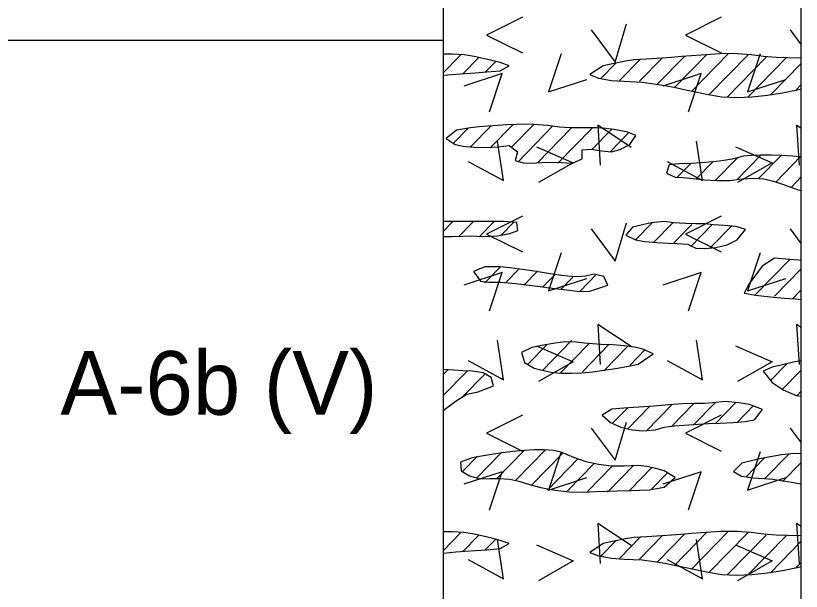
# Model space of a CAD drawing. Extents: x -0.01 to 0.83, y -0.63 to 1.27.
# Drawn here: x 0.7511 to 0.8333, y 0.6598 to 0.7201 of the extents above; entities that cross this region are included whole.
import ezdxf

# ---------------------------------------------------------------- set-up
doc = ezdxf.new("R2010")
doc.units = 0

msp = doc.modelspace()

# ---------------------------------------------------------------- linework, layer by layer
for points in [[(0, 0), (0.833332, 0), (0.833332, 1.274997), (0, 1.274997)], [(0, 0), (0.833332, 0), (0.833332, 1.274997), (0, 1.274997)], [(0, 0), (0.833332, 0), (0.833332, 1.274997), (0, 1.274997)], [(0, 0), (0.833332, 0), (0.833332, 1.274997), (0, 1.274997)], [(0, 0), (0.833332, 0), (0.833332, 1.274997), (0, 1.274997)], [(0.795832, 0.713822), (0.797147, 0.713933), (0.798141, 0.714006), (0.799224, 0.714083), (0.800394, 0.714168), (0.80179, 0.71429), (0.802748, 0.714805), (0.801793, 0.715146), (0.800911, 0.71536), (0.800027, 0.715581), (0.79909, 0.715788), (0.798029, 0.715953), (0.79677, 0.716049), (0.795832, 0.716028)], [(0.828162, 0.711574), (0.82978, 0.711744), (0.831374, 0.711996), (0.832902, 0.712307), (0.833332, 0.712412), (0.833332, 0.715652), (0.832951, 0.715619), (0.831885, 0.715641), (0.830714, 0.715694), (0.829383, 0.715796), (0.828069, 0.715965), (0.826619, 0.716084), (0.825765, 0.716087), (0.824843, 0.71606), (0.823868, 0.716009), (0.822856, 0.71594), (0.82182, 0.715861), (0.820774, 0.715777), (0.819735, 0.715694), (0.818715, 0.715619), (0.817148, 0.715524), (0.815785, 0.715431), (0.814914, 0.715298), (0.813574, 0.715023), (0.812595, 0.714811), (0.811206, 0.713892), (0.812105, 0.71353), (0.813452, 0.713284), (0.814789, 0.713194), (0.816678, 0.713091), (0.818181, 0.712891), (0.819046, 0.712745), (0.820004, 0.712566), (0.821067, 0.712351), (0.82225, 0.7121), (0.823565, 0.711808), (0.825013, 0.711583), (0.826559, 0.711513)], [(0.797084, 0.706593), (0.797938, 0.706415), (0.799042, 0.706303), (0.800285, 0.706269), (0.801555, 0.706323), (0.802742, 0.706478), (0.803614, 0.705816), (0.803377, 0.704919), (0.804221, 0.704648), (0.805167, 0.70463), (0.806129, 0.704685), (0.807202, 0.704717), (0.808182, 0.704685), (0.809387, 0.704612), (0.81037, 0.705078), (0.81038, 0.706025), (0.811296, 0.706087), (0.812442, 0.7059), (0.813463, 0.705794), (0.814379, 0.70605), (0.815394, 0.706592), (0.816006, 0.707505), (0.81517, 0.707878), (0.813738, 0.708154), (0.812849, 0.708247), (0.811872, 0.708305), (0.810001, 0.708307), (0.809104, 0.708325), (0.808002, 0.708399), (0.806784, 0.708556), (0.805305, 0.708686), (0.804427, 0.708699), (0.803488, 0.708684), (0.802511, 0.708643), (0.801521, 0.708581), (0.80054, 0.708503), (0.799593, 0.708412), (0.798702, 0.708313), (0.797221, 0.70809), (0.796138, 0.707212)], [(0.832407, 0.705374), (0.831293, 0.705438), (0.830172, 0.705475), (0.829096, 0.705478), (0.828115, 0.705438), (0.827281, 0.705351), (0.826083, 0.705051), (0.824762, 0.704825), (0.823296, 0.704688), (0.821831, 0.704606), (0.820509, 0.704546), (0.819505, 0.704448), (0.819224, 0.703583), (0.820125, 0.703165), (0.820967, 0.703113), (0.821997, 0.703013), (0.823181, 0.702883), (0.824476, 0.702795), (0.825838, 0.70282), (0.82719, 0.702984), (0.828356, 0.703051), (0.829402, 0.70297), (0.830435, 0.702737), (0.831559, 0.702346), (0.832909, 0.701856), (0.833332, 0.70178), (0.833332, 0.705299)], [(0.795832, 0.696961), (0.796757, 0.696951), (0.797925, 0.69697), (0.798816, 0.697009), (0.799915, 0.696966), (0.801515, 0.69701), (0.802823, 0.697266), (0.803666, 0.697586), (0.80354, 0.698425), (0.802165, 0.69851), (0.795832, 0.69851)], [(0.818216, 0.696316), (0.819444, 0.696257), (0.820325, 0.696217), (0.821453, 0.696149), (0.822286, 0.695735), (0.82324, 0.695691), (0.824378, 0.695796), (0.825554, 0.696084), (0.826624, 0.696589), (0.82749, 0.697686), (0.826513, 0.697989), (0.825239, 0.69809), (0.82413, 0.698154), (0.823236, 0.69826), (0.822257, 0.698279), (0.821211, 0.698303), (0.819948, 0.698394), (0.819024, 0.69851), (0.817611, 0.698371), (0.815663, 0.697927), (0.814958, 0.697088), (0.815983, 0.6966), (0.816947, 0.696424)], [(0.833053, 0.694462), (0.831709, 0.694574), (0.830539, 0.694675), (0.829246, 0.693855), (0.828567, 0.692941), (0.827924, 0.692054), (0.827345, 0.691027), (0.828579, 0.690802), (0.829451, 0.690701), (0.830451, 0.690604), (0.831549, 0.690509), (0.832716, 0.690412), (0.833332, 0.690361), (0.833332, 0.694453)], [(0.800664, 0.692159), (0.801881, 0.692152), (0.803392, 0.692024), (0.804229, 0.691928), (0.805103, 0.691818), (0.806004, 0.6917), (0.806919, 0.691579), (0.807838, 0.691461), (0.808747, 0.691351), (0.810142, 0.691209), (0.811186, 0.691221), (0.812223, 0.691566), (0.81308, 0.691851), (0.812673, 0.692753), (0.811597, 0.693), (0.810749, 0.692802), (0.809892, 0.692719), (0.808847, 0.6928), (0.807995, 0.692911), (0.807033, 0.693055), (0.805997, 0.693218), (0.804922, 0.693386), (0.803843, 0.693543), (0.802797, 0.693675), (0.801817, 0.693767), (0.800202, 0.693776), (0.799007, 0.693303), (0.79974, 0.69226)], [(0.812326, 0.685654), (0.810635, 0.685772), (0.809773, 0.685906), (0.808601, 0.685913), (0.807553, 0.685769), (0.806321, 0.68557), (0.805133, 0.685327), (0.804031, 0.684806), (0.804359, 0.683745), (0.805363, 0.683178), (0.806466, 0.68288), (0.807303, 0.682729), (0.80824, 0.682653), (0.80926, 0.682644), (0.810349, 0.682695), (0.811489, 0.682797), (0.812666, 0.682944), (0.813863, 0.683128), (0.815063, 0.683341), (0.816252, 0.683575), (0.81783, 0.684656), (0.816735, 0.685155), (0.815852, 0.685357), (0.814797, 0.685515), (0.813609, 0.685617)], [(0.832654, 0.683841), (0.831362, 0.683532), (0.830275, 0.683257), (0.829339, 0.682863), (0.830265, 0.681663), (0.831418, 0.6809), (0.832792, 0.680322), (0.833332, 0.680223), (0.833332, 0.683932)], [(0.795832, 0.678745), (0.79719, 0.679735), (0.798312, 0.680437), (0.799509, 0.680708), (0.801112, 0.681309), (0.800861, 0.682193), (0.800021, 0.682669), (0.798893, 0.682863), (0.797908, 0.682893), (0.796943, 0.68295), (0.795832, 0.683032)], [(0.825375, 0.679688), (0.824078, 0.679538), (0.823187, 0.679481), (0.822142, 0.679457), (0.820907, 0.67942), (0.819474, 0.679328), (0.817918, 0.679207), (0.816318, 0.679087), (0.814751, 0.678995), (0.813476, 0.678894), (0.812472, 0.678255), (0.813366, 0.677494), (0.814436, 0.676989), (0.815612, 0.676701), (0.816749, 0.676596), (0.818067, 0.676708), (0.818959, 0.676984), (0.820031, 0.677128), (0.821573, 0.67725), (0.82253, 0.677308), (0.823615, 0.677366), (0.824832, 0.677428), (0.826183, 0.677494), (0.827451, 0.677602), (0.828416, 0.677777), (0.829268, 0.678832), (0.827909, 0.679349), (0.826788, 0.679548)], [(0.798854, 0.673779), (0.797634, 0.673318), (0.797728, 0.672422), (0.798587, 0.671899), (0.799696, 0.671603), (0.800742, 0.671613), (0.801652, 0.671627), (0.802809, 0.671544), (0.803766, 0.671336), (0.804856, 0.670987), (0.80606, 0.67069), (0.807509, 0.670416), (0.809046, 0.67023), (0.810517, 0.6702), (0.811769, 0.670257), (0.812889, 0.670298), (0.814075, 0.670333), (0.815527, 0.670373), (0.816416, 0.670399), (0.817445, 0.670431), (0.818967, 0.670704), (0.820111, 0.67174), (0.818963, 0.672409), (0.818099, 0.672676), (0.817169, 0.672873), (0.816265, 0.672978), (0.814793, 0.672919), (0.813435, 0.672922), (0.812104, 0.673072), (0.810802, 0.673374), (0.809527, 0.673835), (0.808198, 0.674384), (0.807356, 0.674544), (0.806403, 0.674618), (0.805364, 0.674619), (0.804267, 0.674559), (0.803138, 0.67445), (0.802006, 0.674305), (0.800896, 0.674137), (0.799837, 0.673957)], [(0.832629, 0.674225), (0.831261, 0.674088), (0.829688, 0.673823), (0.828826, 0.673649), (0.82712, 0.673238), (0.826226, 0.67237), (0.827084, 0.671878), (0.828308, 0.671691), (0.829408, 0.671626), (0.830335, 0.671537), (0.831655, 0.671354), (0.832526, 0.671212), (0.833332, 0.67107), (0.833332, 0.674218)], [(0.795832, 0.663822), (0.797147, 0.663933), (0.798141, 0.664006), (0.799224, 0.664083), (0.800394, 0.664168), (0.80179, 0.66429), (0.802748, 0.664805), (0.801793, 0.665147), (0.800911, 0.66536), (0.800027, 0.665581), (0.79909, 0.665788), (0.798029, 0.665953), (0.79677, 0.666049), (0.795832, 0.666028)], [(0.828162, 0.661575), (0.82978, 0.661744), (0.831374, 0.661996), (0.832902, 0.662307), (0.833332, 0.662412), (0.833332, 0.665652), (0.832951, 0.665619), (0.831885, 0.665641), (0.830714, 0.665694), (0.829383, 0.665796), (0.828069, 0.665965), (0.826619, 0.666085), (0.825765, 0.666087), (0.824843, 0.66606), (0.823868, 0.666009), (0.822856, 0.66594), (0.82182, 0.665861), (0.820774, 0.665777), (0.819735, 0.665694), (0.818715, 0.665619), (0.817148, 0.665524), (0.815785, 0.665431), (0.814914, 0.665298), (0.813574, 0.665023), (0.812595, 0.664811), (0.811206, 0.663892), (0.812105, 0.66353), (0.813452, 0.663285), (0.814789, 0.663194), (0.816678, 0.663091), (0.818181, 0.662891), (0.819046, 0.662745), (0.820004, 0.662566), (0.821067, 0.662352), (0.82225, 0.6621), (0.823565, 0.661808), (0.825013, 0.661583), (0.826559, 0.661513)]]:
    msp.add_lwpolyline(points, close=True)
for points in [[(0.795832, 1.220831), (0.795832, -0.621832)], [(0.833332, -0.621832), (0.833332, 1.138431)], [(0.804125, 0.719913), (0.800375, 0.718038), (0.804125, 0.716163)], [(0.824958, 0.719913), (0.821208, 0.718038), (0.824958, 0.716163)], [(0.811342, 0.718572), (0.813842, 0.715197), (0.815029, 0.719197)], [(0.832175, 0.718572), (0.833332, 0.717011)], [(0.749999, 0.717499), (0.795832, 0.717499)], [(0.797655, 0.715936), (0.795832, 0.714067)], [(0.799604, 0.71572), (0.797864, 0.713937)], [(0.808181, 0.716082), (0.806868, 0.712082), (0.810868, 0.713394)], [(0.818285, 0.712915), (0.821137, 0.715837)], [(0.820035, 0.712495), (0.823455, 0.716)], [(0.825691, 0.716077), (0.82184, 0.712132)], [(0.827752, 0.715977), (0.823702, 0.711828)], [(0.829644, 0.715702), (0.825565, 0.711524)], [(0.829014, 0.716082), (0.827702, 0.712082), (0.831702, 0.713394)], [(0.801295, 0.71524), (0.800268, 0.714188)], [(0.813923, 0.715083), (0.812354, 0.713476)], [(0.814303, 0.71326), (0.816499, 0.715509)], [(0.816395, 0.71319), (0.818789, 0.715645)], [(0.831735, 0.715633), (0.827743, 0.711543)], [(0.833332, 0.715055), (0.830118, 0.711763)], [(0.800689, 0.710001), (0.802002, 0.714001), (0.798002, 0.712689)], [(0.821523, 0.710001), (0.822835, 0.714001), (0.818835, 0.712689)], [(0.832808, 0.712307), (0.833332, 0.712843)], [(0.798444, 0.708276), (0.796912, 0.706706)], [(0.79871, 0.706336), (0.800849, 0.708527)], [(0.800827, 0.706292), (0.803111, 0.708632)], [(0.805344, 0.708707), (0.802987, 0.706292)], [(0.80367, 0.70478), (0.807321, 0.70852)], [(0.805714, 0.704662), (0.809241, 0.708276)], [(0.811418, 0.708293), (0.807854, 0.70464)], [(0.815512, 0.706275), (0.812012, 0.708588), (0.812262, 0.7044)], [(0.833332, 0.708266), (0.832845, 0.708588), (0.833095, 0.7044)], [(0.811407, 0.706069), (0.81348, 0.708194)], [(0.815282, 0.707828), (0.813313, 0.70581)], [(0.798466, 0.704793), (0.802154, 0.702793), (0.801529, 0.706918)], [(0.8193, 0.704793), (0.822987, 0.702793), (0.822362, 0.706918)], [(0.805617, 0.706338), (0.809456, 0.704655), (0.805806, 0.702593)], [(0.82645, 0.706338), (0.83029, 0.704655), (0.826639, 0.702593)], [(0.824327, 0.702805), (0.82666, 0.705195)], [(0.829094, 0.705477), (0.826565, 0.702885)], [(0.828848, 0.703013), (0.831218, 0.705441)], [(0.833245, 0.705306), (0.830651, 0.702647)], [(0.820346, 0.703151), (0.821763, 0.704603)], [(0.822335, 0.702976), (0.824076, 0.704761)], [(0.833332, 0.703181), (0.832267, 0.702089)], [(0.795832, 0.69748), (0.796808, 0.69848)], [(0.798985, 0.698498), (0.797473, 0.696949)], [(0.801161, 0.698515), (0.799593, 0.696908)], [(0.804125, 0.69908), (0.800375, 0.697205), (0.804125, 0.69533)], [(0.803281, 0.698475), (0.801883, 0.697043)], [(0.819878, 0.698391), (0.817852, 0.696315)], [(0.824958, 0.69908), (0.821208, 0.697205), (0.824958, 0.69533)], [(0.811342, 0.697739), (0.813842, 0.694364), (0.815029, 0.698364)], [(0.817701, 0.698374), (0.815961, 0.696591)], [(0.821854, 0.698203), (0.819972, 0.696274)], [(0.824002, 0.698191), (0.821778, 0.695912)], [(0.826007, 0.698034), (0.823783, 0.695754)], [(0.832175, 0.697739), (0.833332, 0.696178)], [(0.808181, 0.695248), (0.806868, 0.691248), (0.810868, 0.692561)], [(0.829014, 0.695248), (0.827702, 0.691248), (0.831702, 0.692561)], [(0.832167, 0.694588), (0.828441, 0.69077)], [(0.801877, 0.693814), (0.800195, 0.692091)], [(0.803798, 0.69357), (0.80237, 0.692107)], [(0.833332, 0.693569), (0.830521, 0.690689)], [(0.800689, 0.689168), (0.802002, 0.693168), (0.798002, 0.691856)], [(0.805745, 0.693353), (0.804291, 0.691863)], [(0.80758, 0.69302), (0.806268, 0.691675)], [(0.809414, 0.692687), (0.808159, 0.691401)], [(0.811876, 0.692997), (0.810165, 0.691243)], [(0.821523, 0.689168), (0.822835, 0.693168), (0.818835, 0.691856)], [(0.833332, 0.691356), (0.832451, 0.690453)], [(0.815512, 0.685442), (0.812012, 0.687755), (0.812262, 0.683567)], [(0.833332, 0.687433), (0.832845, 0.687755), (0.833095, 0.683567)], [(0.798466, 0.68396), (0.802154, 0.68196), (0.801529, 0.686085)], [(0.806256, 0.68297), (0.809278, 0.686067)], [(0.8193, 0.68396), (0.822987, 0.68196), (0.822362, 0.686085)], [(0.804649, 0.683537), (0.806674, 0.685612)], [(0.805617, 0.685505), (0.809456, 0.683821), (0.805806, 0.68176)], [(0.80809, 0.682637), (0.811113, 0.685734)], [(0.810409, 0.682801), (0.813175, 0.685635)], [(0.812643, 0.682877), (0.815181, 0.685477)], [(0.82645, 0.685505), (0.83029, 0.683821), (0.826639, 0.68176)], [(0.815361, 0.683449), (0.816987, 0.685115)], [(0.830098, 0.681875), (0.831838, 0.683658)], [(0.796303, 0.682991), (0.795832, 0.682507)], [(0.798338, 0.682863), (0.795832, 0.680295)], [(0.831305, 0.6809), (0.833332, 0.682976)], [(0.797862, 0.680163), (0.800229, 0.682588)], [(0.832854, 0.680274), (0.833332, 0.680763)], [(0.822015, 0.677198), (0.824297, 0.679536)], [(0.824306, 0.677333), (0.826445, 0.679525)], [(0.815192, 0.679058), (0.813538, 0.677363)], [(0.815145, 0.676797), (0.817482, 0.679192)], [(0.817092, 0.676579), (0.819744, 0.679296)], [(0.819696, 0.677035), (0.822034, 0.679432)], [(0.826625, 0.677497), (0.828336, 0.67925)], [(0.804125, 0.678247), (0.800375, 0.676372), (0.804125, 0.674497)], [(0.824958, 0.678247), (0.821208, 0.676372), (0.824958, 0.674497)], [(0.811342, 0.676906), (0.813842, 0.673531), (0.815029, 0.677531)], [(0.832175, 0.676906), (0.833332, 0.675344)], [(0.801419, 0.671582), (0.804299, 0.674534)], [(0.806532, 0.67461), (0.803395, 0.671395)], [(0.799375, 0.673915), (0.797863, 0.672365)], [(0.799328, 0.671653), (0.801951, 0.674341)], [(0.805059, 0.670887), (0.808397, 0.674307)], [(0.809973, 0.67371), (0.806747, 0.670404)], [(0.808181, 0.674415), (0.806868, 0.670415), (0.810868, 0.671728)], [(0.827512, 0.671762), (0.82945, 0.673747)], [(0.829014, 0.674415), (0.827702, 0.670415), (0.831702, 0.671728)], [(0.832025, 0.674174), (0.829489, 0.671574)], [(0.811636, 0.673202), (0.808841, 0.670338)], [(0.813527, 0.672926), (0.810936, 0.670272)], [(0.813032, 0.670206), (0.815789, 0.673032)], [(0.831379, 0.671299), (0.833332, 0.6733)], [(0.800689, 0.668335), (0.802002, 0.672335), (0.798002, 0.671022)], [(0.815342, 0.670361), (0.817681, 0.672757)], [(0.817605, 0.670466), (0.819344, 0.672249)], [(0.821523, 0.668335), (0.822835, 0.672335), (0.818835, 0.671022)], [(0.833327, 0.671083), (0.833332, 0.671088)], [(0.815512, 0.664609), (0.812012, 0.666921), (0.812262, 0.662734)], [(0.833332, 0.6666), (0.832845, 0.666921), (0.833095, 0.662734)], [(0.797655, 0.665936), (0.795832, 0.664067)], [(0.799604, 0.66572), (0.797864, 0.663937)], [(0.814303, 0.66326), (0.816499, 0.665509)], [(0.816395, 0.66319), (0.818789, 0.665645)], [(0.818285, 0.662915), (0.821137, 0.665837)], [(0.820035, 0.662495), (0.823455, 0.666)], [(0.825691, 0.666077), (0.82184, 0.662132)], [(0.827752, 0.665977), (0.823702, 0.661828)], [(0.829644, 0.665702), (0.825565, 0.661524)], [(0.831735, 0.665633), (0.827743, 0.661543)], [(0.798466, 0.663126), (0.802154, 0.661126), (0.801529, 0.665251)], [(0.801295, 0.665241), (0.800268, 0.664189)], [(0.805617, 0.664671), (0.809456, 0.662988), (0.805806, 0.660926)], [(0.813923, 0.665083), (0.812354, 0.663476)], [(0.8193, 0.663126), (0.822987, 0.661126), (0.822362, 0.665251)], [(0.82645, 0.664671), (0.83029, 0.662988), (0.826639, 0.660926)], [(0.833332, 0.665056), (0.830118, 0.661763)], [(0.832808, 0.662307), (0.833332, 0.662843)]]:
    msp.add_lwpolyline(points)

# ---------------------------------------------------------------- texts
msp.add_text('A-6b (V)', height=0.0066667).set_placement((0.755748, 0.67829))

doc.saveas('drawing.dxf')
